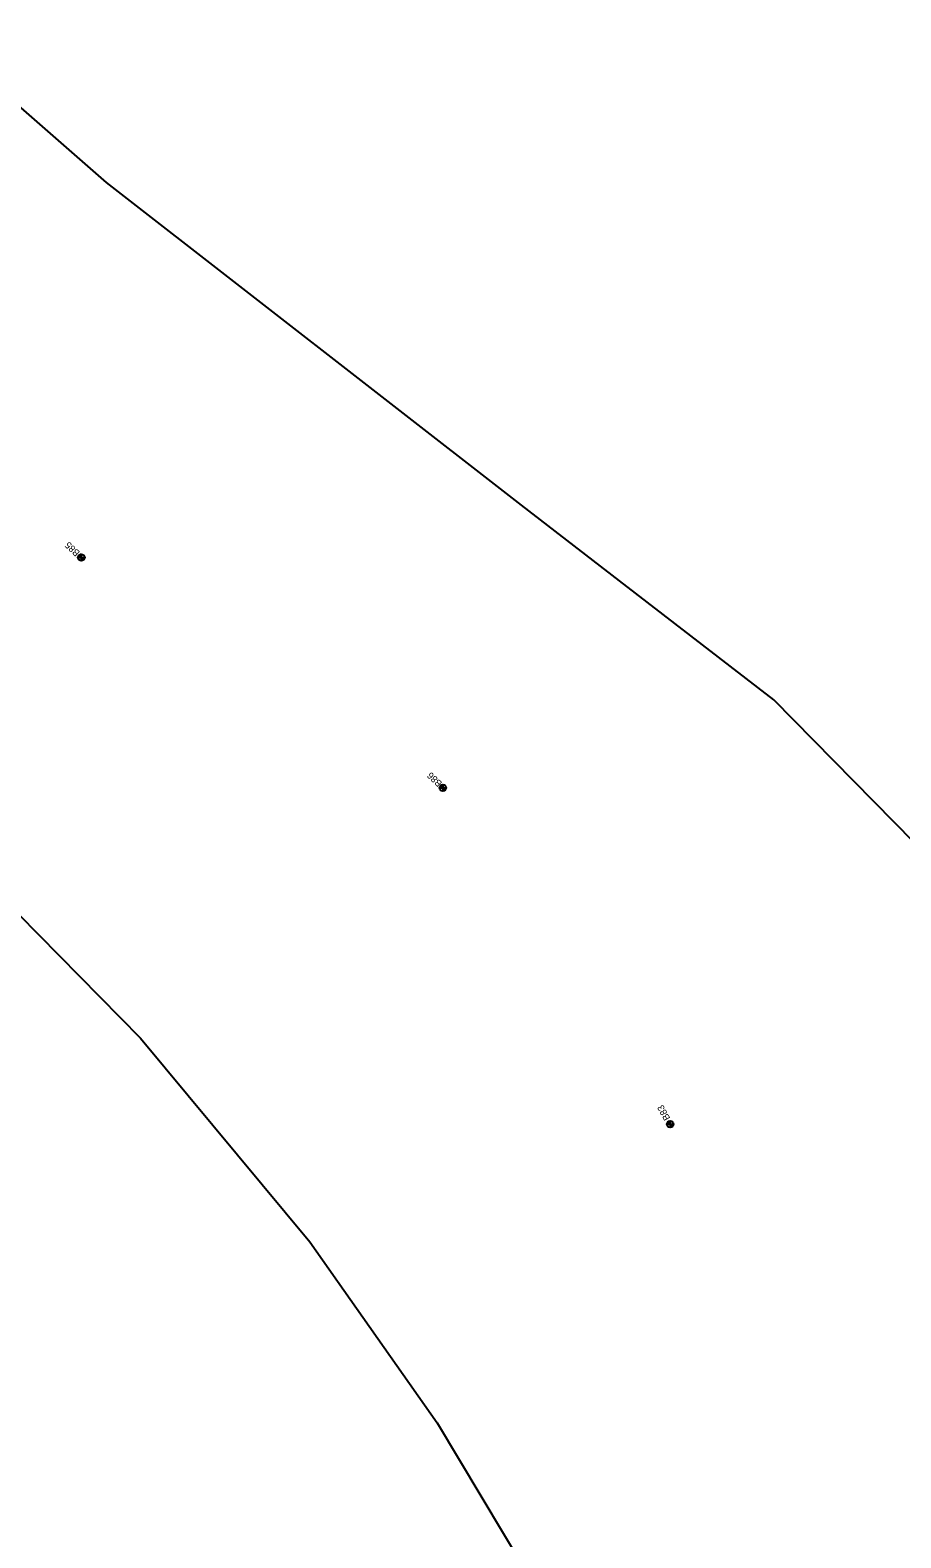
# Model space of a CAD drawing. Extents: x 311409 to 379449, y 121539 to 224848.
# Drawn here: x 358282 to 359583, y 176397 to 178649 of the extents above; entities that cross this region are included whole.
import ezdxf

# ---------------------------------------------------------------- set-up
doc = ezdxf.new("R2010")
doc.units = 0
for name, color, linetype in [('E_SOIL_BORE1 [KAPUR_CADDS_LEVELS]', 7, 'Continuous'), ('E_SOIL_BORE2 [KAPUR_CADDS_LEVELS]', 7, 'Continuous'), ('P_MARK', 7, 'Continuous'), ('P_TC', 7, 'Continuous')]:
    doc.layers.add(name, color=color, linetype=linetype)

msp = doc.modelspace()

# ---------------------------------------------------------------- linework, layer by layer
at = {"layer": 'P_MARK'}
for p, q in [((358353.8, 177861.6), (358363.8, 177861.6)), ((358358.8, 177866.6), (358358.8, 177856.6)), ((358898.7, 177522.5), (358898.7, 177512.5)), ((358893.7, 177517.5), (358903.7, 177517.5)), ((359233.3, 177015.2), (359243.3, 177015.2)), ((359238.3, 177020.2), (359238.3, 177010.2))]:
    msp.add_line(p, q, dxfattribs=at)
for centre in [(358358.8, 177861.6), (358898.7, 177517.5), (359238.3, 177015.2)]:
    msp.add_circle(centre, 5, dxfattribs=at)
for centre, radius, start, end in [((358358.8, 177861.6), 4.5, 89.9869, 179.9869), ((358358.8, 177861.6), 4, 89.9869, 179.9869), ((358358.8, 177861.6), 3.5, 89.9869, 179.9869), ((358358.8, 177861.6), 3, 89.9869, 179.9869), ((358358.8, 177861.6), 2.5, 89.9869, 179.9869), ((358358.8, 177861.6), 2, 89.9869, 179.9869), ((358358.8, 177861.6), 1.5, 89.9869, 179.9869), ((358358.8, 177861.6), 1, 89.9869, 179.9869), ((358358.8, 177861.6), 0.5, 89.9869, 179.9869), ((358358.8, 177861.6), 4.5, 269.9869, 359.9869), ((358358.8, 177861.6), 4, 269.9869, 359.9869), ((358358.8, 177861.6), 3.5, 269.9869, 359.9869), ((358358.8, 177861.6), 3, 269.9869, 359.9869), ((358358.8, 177861.6), 2.5, 269.9869, 359.9869), ((358358.8, 177861.6), 2, 269.9869, 359.9869), ((358358.8, 177861.6), 1.5, 269.9869, 359.9869), ((358358.8, 177861.6), 1, 269.9869, 359.9869), ((358358.8, 177861.6), 0.5, 269.9869, 359.9869), ((358898.7, 177517.5), 4.5, 89.9869, 179.9869), ((358898.7, 177517.5), 4, 89.9869, 179.9869), ((358898.7, 177517.5), 3.5, 89.9869, 179.9869), ((358898.7, 177517.5), 3, 89.9869, 179.9869), ((358898.7, 177517.5), 2.5, 89.9869, 179.9869), ((358898.7, 177517.5), 2, 89.9869, 179.9869), ((358898.7, 177517.5), 1.5, 89.9869, 179.9869), ((358898.7, 177517.5), 1, 89.9869, 179.9869), ((358898.7, 177517.5), 0.5, 89.9869, 179.9869), ((358898.7, 177517.5), 4.5, 269.9869, 359.9869), ((358898.7, 177517.5), 4, 269.9869, 359.9869), ((358898.7, 177517.5), 3.5, 269.9869, 359.9869), ((358898.7, 177517.5), 3, 269.9869, 359.9869), ((358898.7, 177517.5), 2.5, 269.9869, 359.9869), ((358898.7, 177517.5), 2, 269.9869, 359.9869), ((358898.7, 177517.5), 1.5, 269.9869, 359.9869), ((358898.7, 177517.5), 1, 269.9869, 359.9869), ((358898.7, 177517.5), 0.5, 269.9869, 359.9869), ((359238.3, 177015.2), 4.5, 89.9869, 179.9869), ((359238.3, 177015.2), 4, 89.9869, 179.9869), ((359238.3, 177015.2), 3.5, 89.9869, 179.9869), ((359238.3, 177015.2), 3, 89.9869, 179.9869), ((359238.3, 177015.2), 2.5, 89.9869, 179.9869), ((359238.3, 177015.2), 2, 89.9869, 179.9869), ((359238.3, 177015.2), 1.5, 89.9869, 179.9869), ((359238.3, 177015.2), 1, 89.9869, 179.9869), ((359238.3, 177015.2), 0.5, 89.9869, 179.9869), ((359238.3, 177015.2), 4.5, 269.9869, 359.9869), ((359238.3, 177015.2), 4, 269.9869, 359.9869), ((359238.3, 177015.2), 3.5, 269.9869, 359.9869), ((359238.3, 177015.2), 3, 269.9869, 359.9869), ((359238.3, 177015.2), 2.5, 269.9869, 359.9869), ((359238.3, 177015.2), 2, 269.9869, 359.9869), ((359238.3, 177015.2), 1.5, 269.9869, 359.9869), ((359238.3, 177015.2), 1, 269.9869, 359.9869), ((359238.3, 177015.2), 0.5, 269.9869, 359.9869)]:
    msp.add_arc(centre, radius, start, end, dxfattribs=at)
at = {"layer": 'P_TC'}
for points in [[(360564.9, 171534.5), (360796.6, 174469.4), (360628.3, 175702.2), (360517.9, 176032.1), (360348.2, 176426), (360166.8, 176728.9), (359962.3, 177020), (359692, 177345), (359392.9, 177648.7), (359162.3, 177826.9), (359016.4, 177939.7), (358396.6, 178421.6), (358058.1, 178717.6), (357710, 179032.7), (357514.4, 179276.3), (357307.6, 179556.6), (357114.4, 179876.4), (356967.1, 180244.4), (356872.7, 180532.7), (356823.5, 180783.3), (356761.3, 181116.1)], [(355499.6, 180741.3), (355553, 180469.4), (355656.9, 180151.7), (355818.2, 179748.9), (356033.2, 179393.1), (356253, 179095.1), (356469.2, 178825.8), (356481.2, 178815), (356838.9, 178491.2), (357186.7, 178187.1), (357814.4, 177699), (358173.6, 177421.3), (358447.4, 177143.5), (358700.2, 176839.4), (358890.1, 176569.1), (359054, 176295.4), (359209.5, 175934.4), (359313, 175625.5), (359467.9, 174515.5), (359203.4, 171166.2)]]:
    msp.add_lwpolyline(points, dxfattribs=at)

# ---------------------------------------------------------------- texts
at = {"layer": 'E_SOIL_BORE1 [KAPUR_CADDS_LEVELS]'}
msp.add_text('B83', height=10, rotation=118.6843, dxfattribs=at).set_placement((359238.6, 177024.1))
at = {"layer": 'E_SOIL_BORE2 [KAPUR_CADDS_LEVELS]'}
for s, p in [('B85', (358357.4, 177869.4)), ('B86', (358898.3, 177525.3))]:
    msp.add_text(s, height=10, rotation=136.1942, dxfattribs=at).set_placement(p)

doc.saveas('drawing.dxf')
